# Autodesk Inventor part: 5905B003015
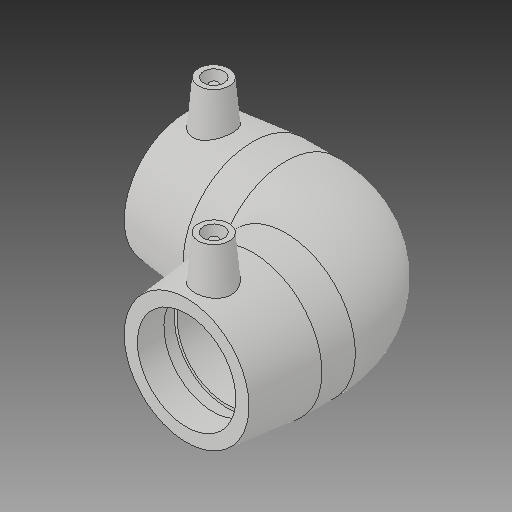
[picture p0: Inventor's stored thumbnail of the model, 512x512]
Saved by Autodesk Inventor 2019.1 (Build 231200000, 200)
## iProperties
Created: 2017-06
Part Number: 5905B003015
Material: Generic
Description: PLASSON 90° ELBOW ASTM 1 1/2''
Document SubType Name: Modeling
Designer: KIM
Mass: 55.0731 g
Surface Area: 148.067 cm^2
Volume: 55.0731 cm^3
Density: 1 g/cm^3
Appearance: Default
Author: KIM
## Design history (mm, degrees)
derived "5905B.ipt"
feature "Solid1::5905B.ipt"
tag "TaggingFeature1"
body "Solid1"
other parameters: "d_" = 48.1, "L_" = 109.474, "L_1" = 48.514, "D_" = 67.818, "A_" = 51.816, "d2" = 67.818, "d4" = 32.19824, "d5" = 61.0362, "d8" = 168 deg, "d10" = 19.4056, "d11" = 6.46853, "d14" = 17.6296, "d18" = 48.1, "d19" = 3.52592, "d20" = 168 deg, "d22" = 62.39256, "d23" = 67.818, "d24" = 60.52078, "d29" = 51.816, "d30" = 15, "d31" = 65.6844, "d34" = 5 deg, "d35" = 15, "d39" = 5 deg, "d41" = 4, "d42" = 14, "d43" = 0, "d45" = 4, "d46" = 14, "d47" = 0, "d49" = 48.1, "d50" = 40.885, "d51" = 19.4056, "d52" = 48.514, "d54" = 90 deg, "d65" = 48.1, "d67" = 45 deg, "d71" = 90 deg, "d75" = 3.3909, "d82" = 45 deg, "d83" = 48.514, "d84" = 61.0362, "d86" = 30.5181, "d87" = 90 deg, "d90" = 48.514, "d91" = 0, "d92" = 48.514, "d93" = 0, "d94" = 90 deg, "d95" = 31.19628, "d98" = 109.474, "d101" = 3, "d102" = 0, "d103" = 3, "d104" = 0, "d105" = 14.06906, "d106" = 3.51727, "d107" = 109.474, "d110" = 26.6827
